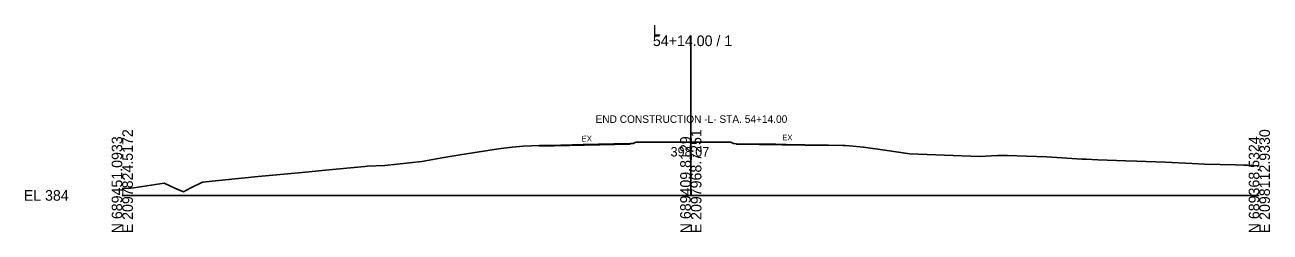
# Model space of a CAD drawing. Extents: x -26 to 8203, y -10 to 9546.
# Drawn here: x 7874.3 to 8202.8, y -9.7 to 45 of the extents above; entities that cross this region are included whole.
import ezdxf

# ---------------------------------------------------------------- set-up
doc = ezdxf.new("R2010")
doc.units = 0
for name, color, linetype in [('Exist CMT Pavement', 7, 'Continuous'), ('Exist Cross Section Cell', 7, 'Continuous'), ('Exist XS Ground Line', 7, 'Continuous'), ('Prop CMT Pvmt Course 1 Wedge', 7, 'Continuous'), ('Prop CMT Pvmt Course 3 Wedge', 7, 'Continuous'), ('Prop CMT Shear Line Text', 7, 'Continuous'), ('Prop XS SE Text', 7, 'Continuous')]:
    doc.layers.add(name, color=color, linetype=linetype)

msp = doc.modelspace()

# ---------------------------------------------------------------- linework, layer by layer
at = {"layer": 'Exist CMT Pavement'}
msp.add_lwpolyline([(7900, 1.84), (7900.59, 1.85), (7902.22, 1.89), (7903.09, 2.01), (7911.06, 3.23), (7913.89, 1.94), (7916.16, 0.98), (7918.1, 2.04), (7921.19, 3.51), (7935.88, 4.97), (7947.47, 6.08), (7953.59, 6.68), (7963.97, 7.66), (7964.59, 7.72), (7969.31, 7.92), (7978.99, 8.99), (7984.81, 10.01), (7989.64, 10.84), (7999.27, 12.35), (8002.91, 12.77), (8005.81, 12.99), (8007.93, 13.06), (8010.09, 13.15), (8015.73, 13.29), (8021.6, 13.45), (8029.69, 13.61), (8034.04, 13.7), (8034.75, 13.7), (8035.48, 14.07), (8036.7, 14.08), (8042.37, 14.07), (8050, 14.07), (8060.54, 14.06), (8061.3, 13.68), (8062.06, 13.67), (8072.44, 13.5), (8075.18, 13.45), (8084.79, 13.3), (8086.34, 13.29), (8090.12, 13.16), (8090.7, 13.15), (8091.83, 13.07), (8095.57, 12.79), (8101.15, 11.99), (8107.82, 11.02), (8119.24, 10.56), (8126.21, 10.28), (8130.94, 10.54), (8133.54, 10.59), (8138.56, 10.34), (8143.94, 10.19), (8153.14, 9.61), (8154.34, 9.54), (8157.36, 9.42), (8164.75, 9.17), (8167.71, 9.04), (8175.15, 8.77), (8182.29, 8.47), (8185.55, 8.27), (8193.7, 8.1), (8195.95, 8.02), (8196.86, 7.99), (8200, 7.86)], dxfattribs=at)
at = {"layer": 'Exist Cross Section Cell'}
for p, q in [((8050, 0), (8050, 42.25)), ((7900, 0), (8050, 0)), ((8050, 0), (8200, 0))]:
    msp.add_line(p, q, dxfattribs=at)
at = {"layer": 'Prop CMT Pvmt Course 1 Wedge'}
for p, q in [((8034, 13.58), (8010, 13)), ((8034, 13.7), (8034, 13.58)), ((8062, 13.67), (8062, 13.54)), ((8062, 13.54), (8086.19, 13.16))]:
    msp.add_line(p, q, dxfattribs=at)
at = {"layer": 'Prop CMT Pvmt Course 3 Wedge'}
for p, q in [((8034, 13.7), (8010, 13.13)), ((8062, 13.67), (8086.19, 13.28)), ((8086.19, 13.28), (8086.19, 13.16)), ((8010, 13.13), (8010, 13))]:
    msp.add_line(p, q, dxfattribs=at)

# ---------------------------------------------------------------- texts
at = {"layer": 'Exist Cross Section Cell'}
for s, p in [('L', (8040, 42.25)), ('54+14.00 / 1', (8040, 39.45)), ('EL 384', (7874, -1.4))]:
    msp.add_text(s, height=2.8, dxfattribs=at).set_placement(p)
for s, p in [('E 2097824.5172', (7902.8, -10)), ('E 2097968.7251', (8052.8, -10)), ('E 2098112.9330', (8202.8, -10)), ('N 689451.0933', (7900, -10)), ('N 689409.8129', (8050, -10)), ('N 689368.5324', (8200, -10))]:
    msp.add_text(s, height=2.8, rotation=90, dxfattribs=at).set_placement(p)
at = {"layer": 'Exist XS Ground Line'}
msp.add_text('398.07', height=2.5, dxfattribs=at).set_placement((8044.65, 10.28))
at = {"layer": 'Prop CMT Shear Line Text'}
msp.add_text('END CONSTRUCTION -L- STA. 54+14.00', height=2, dxfattribs=at).set_placement((8024.86, 19.16))
at = {"layer": 'Prop XS SE Text'}
for rotation, p in [(1.1458, (8021.23, 14.23)), (358.9331, (8074.12, 14.59))]:
    msp.add_text('EX', height=1.5, rotation=rotation, dxfattribs=at).set_placement(p)

doc.saveas('drawing.dxf')
